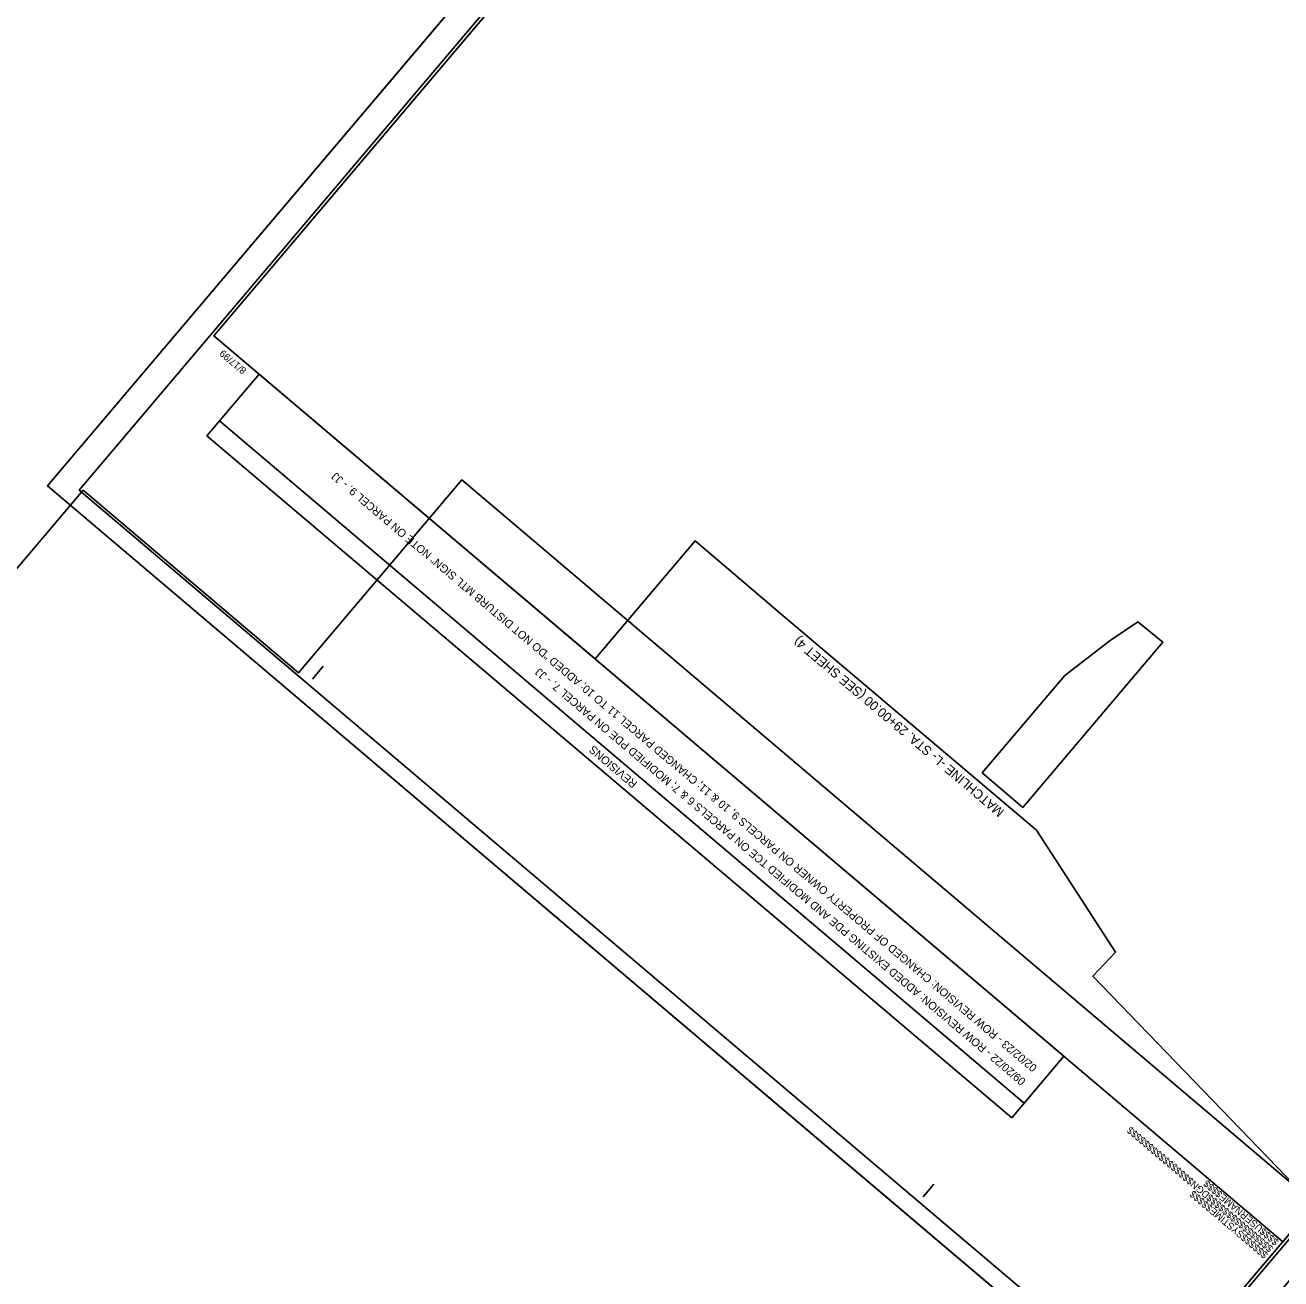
# Model space of a CAD drawing. Extents: x 1761124 to 1763803, y 421930 to 424918.
# Drawn here: x 1761863 to 1762804, y 422941 to 423880 of the extents above; entities that cross this region are included whole.
import ezdxf

# ---------------------------------------------------------------- set-up
doc = ezdxf.new("R2010")
doc.units = 0
for name, color, linetype in [('CTL Primary Horizontal and Vertical Cogo Number', 7, 'Continuous'), ('CTL Sheet Datum Description CELL', 7, 'Continuous'), ('Exist Building', 7, 'Continuous'), ('Exist Hydro Stream or Body of Water', 7, 'Continuous'), ('Exist Other Culture Sign Post CELL', 7, 'Continuous'), ('Exist Roads Change in Surface', 7, 'Continuous'), ('Exist Roads Change in Surface Text', 7, 'Continuous'), ('Exist Roads EOP Other', 7, 'Continuous'), ('Exist Roads EOT', 7, 'Continuous'), ('Exist Roads Soil', 7, 'Continuous'), ('Exist Structure Major Deck Tunnel Box Culvert', 7, 'Continuous')]:
    doc.layers.add(name, color=color, linetype=linetype)

msp = doc.modelspace()

# ---------------------------------------------------------------- linework, layer by layer
at = {"layer": 'CTL Primary Horizontal and Vertical Cogo Number'}
msp.add_lwpolyline([(1761924.97, 421929.51), (1762829.92, 422997.73), (1762190.13, 423539.73), (1762067.79, 423395.32), (1761906.43, 423532.03), (1761123.81, 422608.21)], close=True, dxfattribs=at)
at = {"layer": 'CTL Sheet Datum Description CELL'}
msp.add_lwpolyline([(1762004.42, 423647.67), (1762290.12, 423405.67), (1762365.05, 423494.02), (1762431.11, 423438.06), (1762620.91, 423277.27), (1762680.29, 423186), (1762663.1, 423167.95), (1762828.75, 422996.34), (1763720.34, 424048.79), (1763103.2, 424571.6), (1763016.39, 424468.96), (1762832.28, 424624.92), (1762079.3, 423736.09)], close=True, dxfattribs=at)
at = {"layer": 'Exist Building'}
msp.add_lwpolyline([(1762580.2, 423320.37), (1762642.26, 423393.14), (1762676.13, 423419.39), (1762696.87, 423433.36), (1762715.69, 423418.21), (1762610.82, 423294.43)], close=True, dxfattribs=at)
at = {"layer": 'Exist Other Culture Sign Post CELL'}
msp.add_line((1762620.91, 423277.27), (1762431.11, 423438.06), dxfattribs=at)
at = {"layer": 'Exist Roads Change in Surface'}
msp.add_lwpolyline([(1762715.14, 422827.41), (1763803.34, 424111.93), (1762967.84, 424819.73), (1761879.65, 423535.21)], close=True, dxfattribs=at)
at = {"layer": 'Exist Roads Change in Surface Text'}
for p, q in [((1762967.84, 424819.73), (1761879.65, 423535.21)), ((1761879.65, 423535.21), (1762715.14, 422827.41))]:
    msp.add_line(p, q, dxfattribs=at)
at = {"layer": 'Exist Roads EOP Other'}
for p, q in [((1762004.42, 423647.7), (1762004.42, 423647.7)), ((1762078.22, 423390.56), (1762086.29, 423400.12)), ((1762536.03, 423002.75), (1762544.12, 423012.28))]:
    msp.add_line(p, q, dxfattribs=at)
for points in [[(1762974.03, 424792.24), (1762004.42, 423647.7), (1762805.58, 422968.99), (1763775.17, 424113.51)], [(1762805.58, 422968.99), (1762004.42, 423647.67), (1762844.69, 424639.59), (1762959.2, 424542.6), (1763088.51, 424695.22), (1763775.17, 424113.51)]]:
    msp.add_lwpolyline(points, close=True, dxfattribs=at)
at = {"layer": 'Exist Roads EOT'}
msp.add_line((1762611.81, 423072.89), (1762008.54, 423583.94), dxfattribs=at)
msp.add_lwpolyline([(1762602.43, 423061.77), (1761999.16, 423572.84), (1762038.27, 423619.04), (1762641.54, 423107.98)], close=True, dxfattribs=at)
at = {"layer": 'Exist Roads Soil'}
msp.add_lwpolyline([(1762708.28, 422850.26), (1763785.15, 424121.43), (1762980.19, 424803.37), (1761903.31, 423532.2)], close=True, dxfattribs=at)
at = {"layer": 'Exist Structure Major Deck Tunnel Box Culvert'}
msp.add_lwpolyline([(1762004.42, 423647.67), (1762805.58, 422968.99), (1763775.16, 424113.5), (1763135.37, 424655.51), (1762980.72, 424472.96), (1762819.36, 424609.66)], close=True, dxfattribs=at)

# ---------------------------------------------------------------- texts
at = {"layer": 'Exist Hydro Stream or Body of Water'}
msp.add_text('MATCHLINE -L- STA. 29+00.00 (SEE SHEET 4)', height=7, rotation=139.7301, dxfattribs=at).set_placement((1762597.29, 423292.03))
at = {"layer": 'Exist Roads EOP Other'}
for s, p in [('8/17/99', (1762029.21, 423622.47)), ('$$$$$$$$$$$$$$$$DGN$$$$$$$$$$$$$$$$', (1762798.84, 422964.69)), ('$$$$$$SYSTIME$$$$$', (1762794.93, 422960.04)), ('$$$$USERNAME$$$$', (1762803.06, 422969.7))]:
    msp.add_text(s, height=5.25, rotation=139.73011, dxfattribs=at).set_placement(p)
at = {"layer": 'Exist Roads EOT'}
for s, p in [('02/02/23 - ROW REVISION: CHANGED OF PROPERTY OWNER ON PARCELS 9, 10 & 11; CHANGED PARCEL 11 TO 10; ADDED "DO NOT DISTURB MTL SIGN" NOTE ON PARCEL 9. - JJ ', (1762621.89, 423100.2)), ('09/20/22 - ROW REVISION: ADDED EXISTING PDE AND MODIFIED TCE ON PARCELS 6 & 7; MODIFIED PDE ON PARCEL 7. - JJ ', (1762613.39, 423090.16)), ('REVISIONS', (1762322.19, 423312.94))]:
    msp.add_text(s, height=6, rotation=139.7301, dxfattribs=at).set_placement(p)

doc.saveas('drawing.dxf')
